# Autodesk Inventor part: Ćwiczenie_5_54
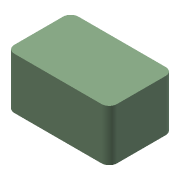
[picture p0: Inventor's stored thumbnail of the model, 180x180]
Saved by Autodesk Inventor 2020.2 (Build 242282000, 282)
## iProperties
Created: 2005-05
Part Number: Ćwiczenie_5_54
Document SubType Name: Modeling
Designer: F.Stasiak
Manufacturer: Standard
Standards Organization: Custom
Density: 1 g/cm^3
Material: Ogólny
Appearance: Zielony pastelowy
Manager: www.cadconsulting.pl
Company: Fabian Stasiak CAD Consulting
Author: F.Stasiak
Subject: Zbiór ćwiczeń. Autodesk Inventor 2020. Kurs podstawowy
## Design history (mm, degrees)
sketch "Szkic1"
  geometry: L1 (-40, 25)-(40, 25); L2 (40, 25)-(40, -25); L3 (40, -25)-(-40, -25); L4 (-40, -25)-(-40, 25); L5 (0, 25)-(0, -25); 2 further points
  constraints: 10 end point, 3 midpoint, 2 parallel, 1 coincident, 1 horizontal, 1 perpendicular
  dimensions: "d0" = 80 distance of L2.end L3.end; "d1" = 50 distance of L1.end L2.end
extrude "Wyciągnięcie proste1" new body sketch "Szkic1" distance "d2" = 40; taper "d3" = 0 deg
fillet "Zaokrąglenie1" dims "d4" = 6
node "Bryła1"
node "Korpusy bryłowe"
node "Korpusy powierzchniowe"
